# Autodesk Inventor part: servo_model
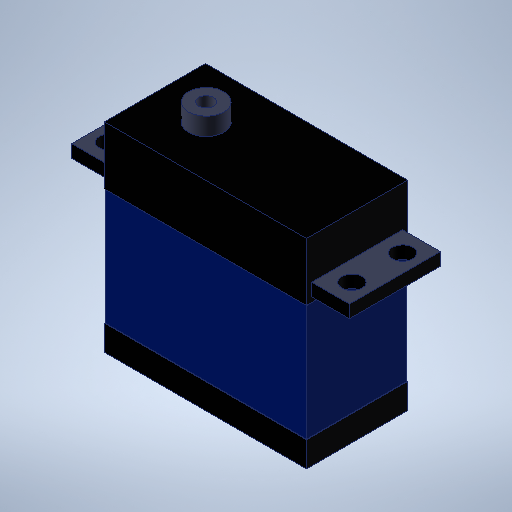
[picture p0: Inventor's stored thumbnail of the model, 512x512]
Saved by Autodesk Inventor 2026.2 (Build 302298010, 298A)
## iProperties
Created: 1705-05
Part Number: servo_model
Material: Générique
Document SubType Name: Modeling
Designer: mel
Density: 1 g/cm^3
Appearance: Par défaut
Sending System: SOLIDWORKS 2017
Last Saved Date: 2023-06-07
Author: mel
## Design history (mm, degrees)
feature "Symétrie2"
sketch "Esquisse1"
  geometry: C1 r 1.5 at (0, 0) reference; 1 further point
extrude "Extrusion1" cut sketch "Esquisse1" distance "d0" = 10; taper "d1" = 0 deg
sketch "Esquisse3"
  geometry: L1 (0, 0)-(7.5, 0) reference; L2 (0, -18)-(0, 0) reference; L3 (0, -18)-(7.5, -18) reference; L4 (7.5, -18)-(7.5, 0) reference; L5 (-47.5, 0)-(-40, 0) reference; L6 (-47.5, -18)-(-47.5, 0) reference; L7 (-47.5, -18)-(-40, -18) reference; L8 (-40, -18)-(-40, 0) reference; C1 r 2 at (4, -14) reference; C2 r 2 at (4, -4) reference; C3 r 2 at (-44, -4) reference; C4 r 2 at (-44, -14) reference; 1 further point
extrude "Extrusion2" join sketch "Esquisse3" distance "d2" = 3; taper "d3" = 0 deg
sketch "Esquisse4"
  geometry: L1 (7.5, 0)-(0, 0) reference; L2 (7.5, 18)-(7.5, 0) reference; L3 (7.5, 18)-(0, 18) reference; L4 (0, 18)-(0, 0) reference; L5 (-40, 0)-(-47.5, 0) reference; L6 (-40, 18)-(-40, 0) reference; L7 (-40, 18)-(-47.5, 18) reference; L8 (-47.5, 18)-(-47.5, 0) reference; C1 r 2 at (4, 14) reference; C2 r 2 at (4, 4) reference; C3 r 2 at (-44, 4) reference; C4 r 2 at (-44, 14) reference; 1 further point
extrude "Extrusion3" cut sketch "Esquisse4" distance "d4" = 3; taper "d5" = 0 deg
node "Solide1"
node "Boucle projetée1"
node "Boucle projetée2"
node "Boucle projetée3"
node "Boucle projetée4"
